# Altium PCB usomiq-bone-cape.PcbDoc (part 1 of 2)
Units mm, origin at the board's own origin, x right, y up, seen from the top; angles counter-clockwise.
Board outline 86.36 x 54.61 mm, 2 copper layers (Top Layer, Bottom Layer); 72 components, 131 nets, 473 pads, 192 vias.
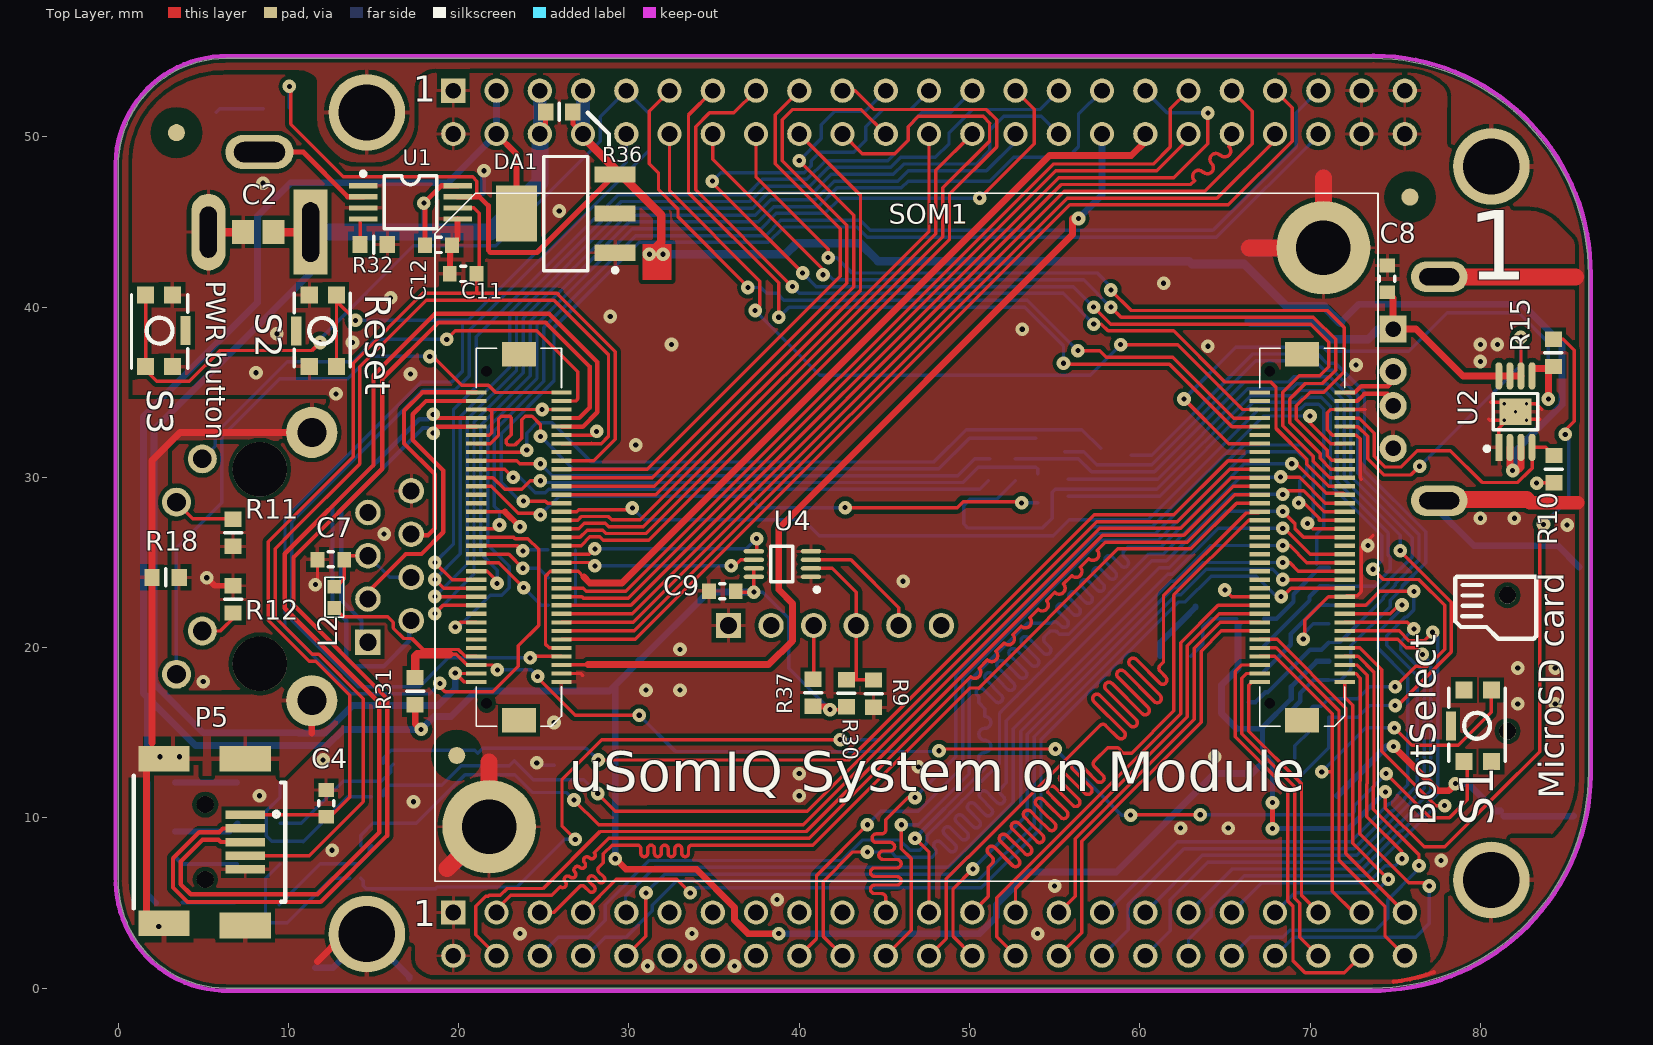
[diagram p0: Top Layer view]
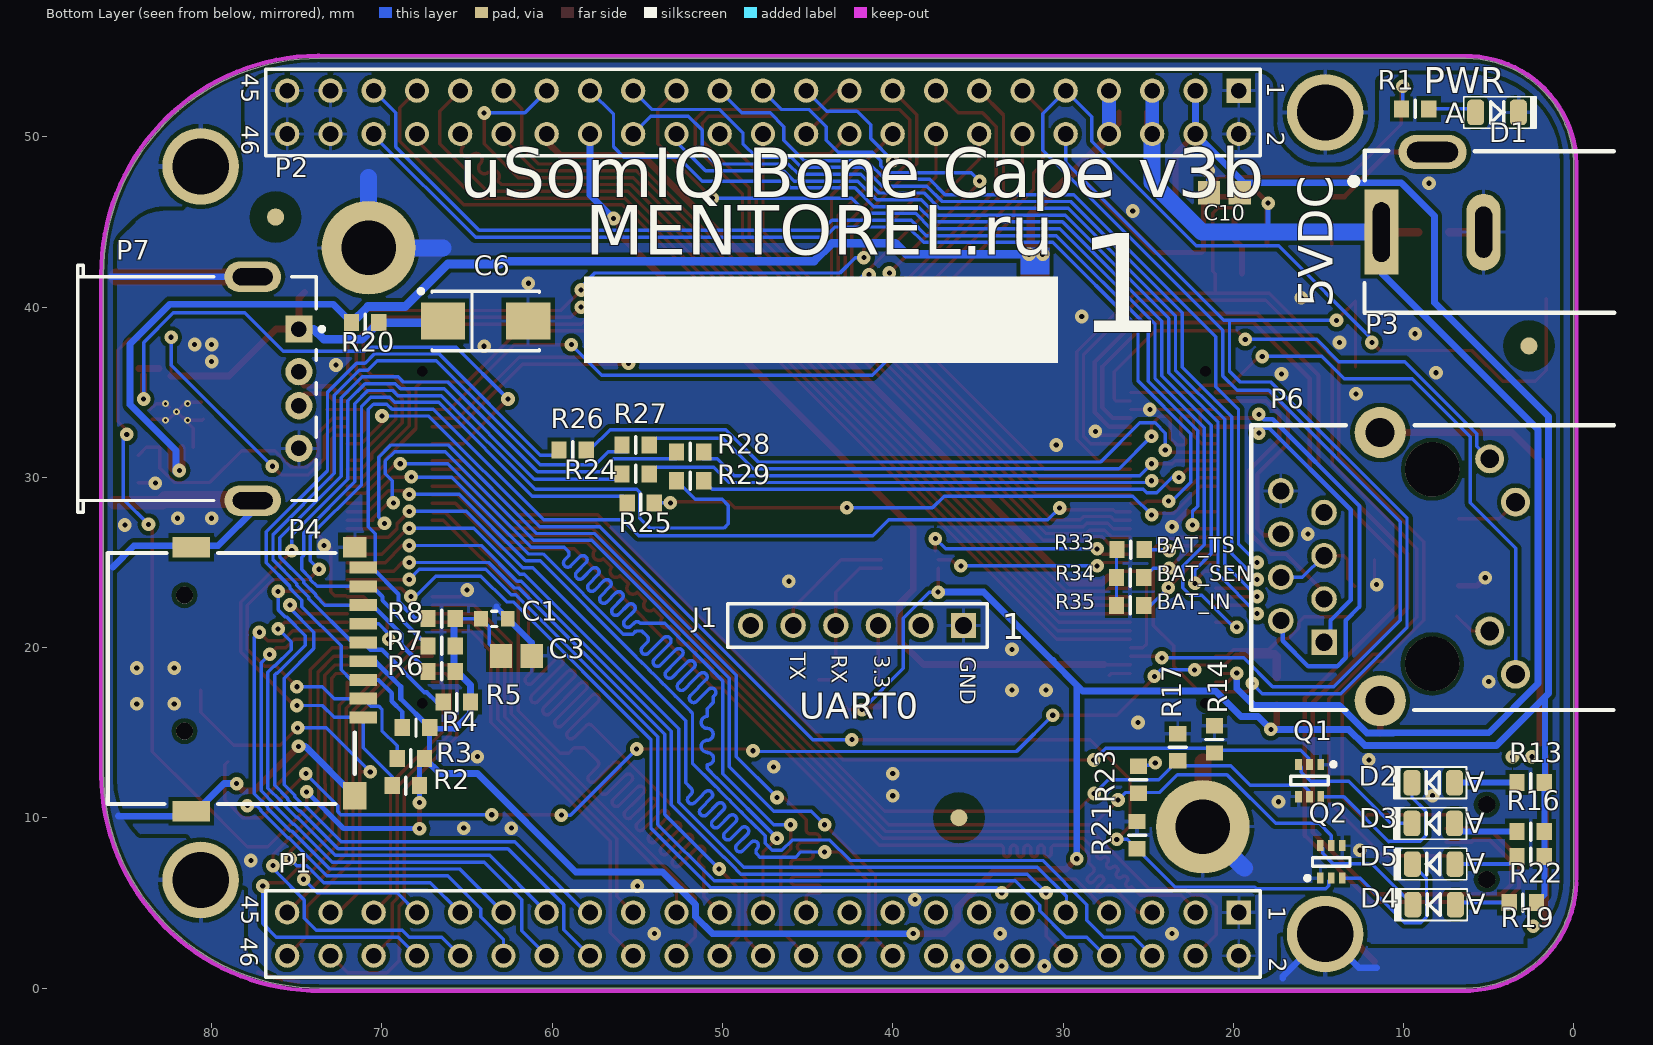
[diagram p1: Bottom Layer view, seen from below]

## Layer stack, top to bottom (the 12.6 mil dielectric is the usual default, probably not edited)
Top Solder: solder mask 0.0102, Solder Resist, Dk 3.5
Top Layer: signal copper 0.0356
Dielectric1: dielectric 0.32, FR-4, Dk 4.8
Bottom Layer: signal copper 0.0356
Bottom Solder: solder mask 0.0102, Solder Resist, Dk 3.5

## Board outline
0,6.35 0,48.26 cw(c6.35,48.26) 6.35,54.61 73.66,54.61 cw(c73.66,41.91) 86.36,41.91 86.36,12.7 cw(c73.66,12.7) 73.66,0 6.35,0 cw(c6.35,6.35)

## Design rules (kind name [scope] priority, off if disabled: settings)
AssemblyTestPointUsage [All] p1 off:
AssemblyTestPointUsage AssemblyTestPointUsage_1 [All] p2 off:
AssemblyTestpoint [All] p1 off: testpointundercomponent=TRUE minsize=1.016 maxsize=2.54 preferedsize=1.524 minholesize=0 maxholesize=1.016 preferedholesize=0.813 testpointgrid=0.025 usegrid=TRUE gridtolerance=0 allowsidetop=TRUE allowsidebottom=TRUE
AssemblyTestpoint AssemblyTestpoint_1 [All] p2 off: testpointundercomponent=TRUE minsize=1.016 maxsize=2.54 preferedsize=1.524 minholesize=0 maxholesize=1.016 preferedholesize=0.813 testpointgrid=0.025 usegrid=TRUE gridtolerance=0 allowsidetop=TRUE allowsidebottom=TRUE
Clearance Clearance_2 [InPolygon] p1: gap=0.25
Clearance Clearance_1 [InPolygon vs OnLayer('Keep-Out Layer')] p2: gap=0.25
Clearance [All] p3: gap=0.2
ComponentClearance [All] p1 off: gap=0.254 collisioncheckmode=3 verticalgap=0.254 showdistances=FALSE
ComponentClearance ComponentClearance_1 [All] p2 off: gap=0.254 collisioncheckmode=3 verticalgap=0.254 showdistances=FALSE
DiffPairsRouting [InNetClass('DIFF')] p1: maxlimit=0.254 minlimit=0.254 mostfreqgap=0.254 toplayer_minwidth=0.381 toplayer_maxwidth=0.381 toplayer_prefwidth=0.381 bottomlayer_minwidth=0.381 bottomlayer_maxwidth=0.381 bottomlayer_prefwidth=0.381 maxuncoupledlength=12.7
FabricationTestPointUsage [All] p1 off: valid=0 allowmultiple=FALSE
FabricationTestPointUsage FabricationTestPointUsage_1 [All] p2 off: valid=0 allowmultiple=FALSE
FabricationTestpoint [All] p1 off: side=3 testpointundercomponent=TRUE minsize=1.016 maxsize=2.54 preferedsize=1.524 minholesize=0 maxholesize=1.016 preferedholesize=0.813 testpointgrid=0.025 allowsidetop=TRUE allowsidebottom=TRUE usegrid=TRUE gridtolerance=0
FabricationTestpoint FabricationTestpoint_1 [All] p2 off: side=3 testpointundercomponent=TRUE minsize=1.016 maxsize=2.54 preferedsize=1.524 minholesize=0 maxholesize=1.016 preferedholesize=0.813 testpointgrid=0.025 allowsidetop=TRUE allowsidebottom=TRUE usegrid=TRUE gridtolerance=0
FanoutControl Fanout_LCC [IsLCC] p1: bgadir=Out bgaviamode=Centered fanoutstyle=Auto fanoutdirection=Alternating viagrid=0.025 // Fanout_LCC (Default Rule)
FanoutControl Fanout_BGA [IsBGA] p2: bgadir=Out bgaviamode=Centered fanoutstyle=Auto fanoutdirection=Alternating viagrid=0.025 // Fanout_BGA (Default Rule)
FanoutControl Fanout_Default [All] p4: bgadir=Out bgaviamode=Centered fanoutstyle=Auto fanoutdirection=Alternating viagrid=0.025 // Fanout_Default (Default Rule)
FanoutControl Fanout_Small [(CompPinCount < 5)] p5: bgadir=Out bgaviamode=Centered fanoutstyle=Auto fanoutdirection=OutThenIn viagrid=0.025 // Fanout_Small (Default Rule)
FanoutControl Fanout_BGA_1 [IsBGA] p6: bgadir=Out bgaviamode=Centered fanoutstyle=Auto fanoutdirection=Alternating viagrid=0.025 // Fanout_BGA (Default Rule)
FanoutControl Fanout_LCC_1 [IsLCC] p7: bgadir=Out bgaviamode=Centered fanoutstyle=Auto fanoutdirection=Alternating viagrid=0.025 // Fanout_LCC (Default Rule)
FanoutControl Fanout_SOIC_1 [IsSOIC] p8: bgadir=Out bgaviamode=Centered fanoutstyle=Auto fanoutdirection=Alternating viagrid=0.025 // Fanout_SOIC (Default Rule)
FanoutControl Fanout_Small_1 [(CompPinCount < 5)] p9: bgadir=Out bgaviamode=Centered fanoutstyle=Auto fanoutdirection=OutThenIn viagrid=0.025 // Fanout_Small (Default Rule)
FanoutControl Fanout_Default_1 [All] p10: bgadir=Out bgaviamode=Centered fanoutstyle=Auto fanoutdirection=Alternating viagrid=0.025 // Fanout_Default (Default Rule)
Height [All] p1 off: minheight=0 maxheight=25.4 prefheight=12.7
Height Height_1 [All] p2 off: minheight=0 maxheight=25.4 prefheight=12.7
HoleSize [All] p1 off: absolutevalues=TRUE maxlimit=2.54 minlimit=0.025 maxpercent=80.000 minpercent=20.000
HoleSize HoleSize_1 [All] p2 off: absolutevalues=TRUE maxlimit=2.54 minlimit=0.025 maxpercent=80.000 minpercent=20.000
HoleToHoleClearance [All] p1 off: gap=0.254 allowstackedmicrovias=TRUE
HoleToHoleClearance HoleToHoleClearance_1 [All] p2 off: gap=0.254 allowstackedmicrovias=TRUE
LayerPairs [All] p1 off: enforce=TRUE
LayerPairs LayerPairs_1 [All] p2 off: enforce=TRUE
Length Length_MMC1 [(InNetClass('MMC1'))] p1: maxlimit=62.1 minlimit=56.1
MinimumSolderMaskSliver [All] p1 off: minsoldermaskwidth=0.254
MinimumSolderMaskSliver MinimumSolderMaskSliver_1 [All] p2 off: minsoldermaskwidth=0.254
NetAntennae [All] p1 off: netantennaetolerance=0
NetAntennae NetAntennae_1 [All] p2 off: netantennaetolerance=0
PasteMaskExpansion PasteMaskExpansion_1 [All] p2: expansion=0
PlaneConnect [All] p1: planeconnectstyle=Relief reliefexpansion=0.2 reliefentries=4 reliefconductorwidth=0.2 reliefairgap=0.2
PolygonConnect PolygonConnect_EARTH [All vs InNet(EARTH)] p1: connectstyle=Relief reliefconductorwidth=0.254 reliefentries=4 polygonreliefangle="90 Angle" airgapwidth=0.254
PolygonConnect PolygonConnect_Via [IsVia] p2: connectstyle=Direct reliefconductorwidth=0.254 reliefentries=4 polygonreliefangle="90 Angle" airgapwidth=0.254
PolygonConnect [All] p3: connectstyle=Relief reliefconductorwidth=0.2 reliefentries=4 polygonreliefangle="90 Angle" airgapwidth=0.254
RoutingPriority RoutingPriority_1 [All] p2: routingpriority=0
RoutingTopology RoutingTopology_1 [All] p2: topology=Shortest
RoutingVias [All] p1: holewidth=0.4 width=0.8 viastyle="Through Hole" minholewidth=0.4 minwidth=0.8 maxholewidth=0.4 maxwidth=0.8
SilkToSilkClearance [All] p1 off: silktosilkclearance=0.254
SilkToSilkClearance SilkToSilkClearance_1 [All] p2 off: silktosilkclearance=0.254
SilkToSolderMaskClearance SilkscreenOverComponentPads [IsPad] p1 off: minsilkscreentomaskgap=0.1 clearancetoexposedcopper=TRUE
SilkToSolderMaskClearance SilkscreenOverComponentPads_1 [IsPad] p2 off: minsilkscreentomaskgap=0.1 clearancetoexposedcopper=TRUE
SolderMaskExpansion [All] p1: expansion=0.102
SolderMaskExpansion SolderMaskExpansion_1 [All] p2: expansion=0.102
UnRoutedNet UnRoutedNet_1 [All] p2:
Width Width_diff [InNetClass('DIFF')] p1: maxlimit=0.254 minlimit=0.254 preferedwidth=0.254
Width [All] p2: maxlimit=1 minlimit=0.2 preferedwidth=0.2
10 further rules are at their usual default settings.

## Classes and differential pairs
component class bone_capes: P1 P2
component class usomiq: SOM1
differential pair ETH_RX: +ETH_RX_P -ETH_RX_N
differential pair ETH_TX: +ETH_TX_P -ETH_TX_N
differential pair USB0_D: +USB0_D_P -USB0_D_N
differential pair USB1: +USB1_P -USB1_N

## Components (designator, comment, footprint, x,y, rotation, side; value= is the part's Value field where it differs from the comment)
C1 "C0603" CC1608-0603 63.4,21.7 r180 bottom
C2 "C0805" CC2012-0805 8.23,44.399 r0 top
C3 "C0805" CC2012-0805 62.1,19.5 r0 bottom
C4 "C0603" CC1608-0603 12.219,10.855 r90 top locked
C6 "Cap_C" Cap_C 63.914,39.182 r180 bottom locked
C7 "C0603" CC1608-0603 12.497,25.171 r180 top
C8 "C0603" CC1608-0603 74.539,41.657 r270 top locked
C9 "C0603" CC1608-0603 35.484,23.317 r0 top
C10 "C0805" CC2012-0805 20.523,46.711 r180 bottom
C11 "C0603" CC1608-0603 20.269,41.961 r0 top
C12 "C0603" CC1608-0603 18.821,43.637 r180 top
D1 "LED0805" LED0805 5.766,51.435 r180 bottom
D2 "LED0805" LED0805 7.01,12.065 r0 bottom
D3 "LED0805" LED0805 7.01,9.677 r0 bottom
D4 "LED0805" LED0805 6.96,4.902 r0 bottom
D5 "LED0805" LED0805 6.985,7.29 r0 bottom
DA1 "LM1117" SOT230P700X160-4N 26.289,45.491 r180 top
J1 "HEADER 6" DIP6 35.85,21.3 r270 bottom locked
L2 "BLM18A-FB" CHIP0603 12.7,22.327 r90 top
P1 "HDR_46_F_2_0.1_0.1" DIP46 19.685,4.445 r270 bottom locked
P2 "HDR_46_F_2_0.1_0.1" DIP46 19.685,52.705 r270 bottom locked
P3 "PJ-002A" PJ-002A 11.303,44.399 r90 bottom
P4 "" TFC08WP01F-A-R1K-H 71.1,15.9 r270 bottom locked
P5 "MiniUSB-B" "MINI-USB-B5 SMT" 1.219,13.081 r0 top
P6 "CONN_RJ45_MAG_WE_0" TRJ0011ABNL 14.675,20.315 r90 bottom locked
P7 "CONN_54819-0578_2" USB2.5-2H4C 87.869,35.205 r0 bottom locked
Q1 "RN1907" SOT363-6L 15.519,12.192 r270 bottom
Q2 "RN1907" SOT363-6L 14.249,7.417 r90 bottom
R1 "R0603" RESC1608X55N 9.322,51.638 r0 bottom
R2 "R0603" RESC1608X55N 68.6,11.9 r180 bottom
R3 "R0603" RESC1608X55N 68.3,13.5 r180 bottom
R4 "R0603" RESC1608X55N 68,15.3 r180 bottom
R5 "R0603" RESC1608X55N 65.6,16.8 r180 bottom
R6 "R0603" RESC1608X55N 66.5,18.6 r180 bottom
R7 "R0603" RESC1608X55N 66.5,20.1 r180 bottom
R8 "R0603" RESC1608X55N 66.5,21.7 r180 bottom
R9 "R0603" RESC1608X55N 44.374,17.297 r90 top
R10 "R0603" RESC1608X55N 84.314,30.482 r90 top locked
R11 "R0603" RESC1608X55N 6.756,26.746 r90 top
R12 "R0603" RESC1608X55N 6.756,22.835 r270 top
R13 "R0603" RESC1608X55N 2.54,12.09 r180 bottom
R14 "R0603" RESC1608X55N 21.114,14.607 r270 bottom
R15 "R0603" RESC1608X55N 84.289,37.307 r90 top
R16 "R0603" RESC1608X55N 2.54,9.195 r180 bottom
R17 "R0603" RESC1608X55N 23.266,14.148 r270 bottom
R18 "R0603" RESC1608X55N 2.794,24.13 r180 top locked
R19 "R0603" RESC1608X55N 2.997,5.029 r180 bottom
R20 "R0603" RESC1608X55N 70.989,39.082 r0 bottom
R21 "R0603" RESC1608X55N 25.654,8.992 r270 bottom
R22 "R0603" RESC1608X55N 2.54,7.722 r180 bottom
R23 "R0603" RESC1608X55N 25.578,12.243 r270 bottom
R24 "R0603" RESC1608X55N 55.1,30.2 r180 bottom
R25 "R0603" RESC1608X55N 54.8,28.5 r180 bottom
R26 "R0603" RESC1608X55N 58.8,31.6 r180 bottom
R27 "R0603" RESC1608X55N 55.1,31.9 r180 bottom
R28 "R0603" RESC1608X55N 51.9,31.5 r180 bottom
R29 "R0603" RESC1608X55N 51.9,29.8 r180 bottom
R30 "R0603" RESC1608X55N 42.774,17.323 r270 top
R31 "R0603" RESC1608X55N 17.45,17.45 r90 top
R32 "R0603" RESC1608X55N 15.011,43.663 r0 top
R33 "R0603" RESC1608X55N 26.035,25.756 r0 bottom
R34 "R0603" RESC1608X55N 26.06,24.105 r0 bottom
R35 "R0603" RESC1608X55N 26.06,22.479 r0 bottom
R36 "R0603" RESC1608X55N 25.908,51.46 r0 top
R37 "R0603" RESC1608X55N 40.818,17.348 r270 top
S1 "SW_KT11P2JM_2" KMR231GLFS 79.045,13.31 r90 top
S2 "SW_KT11P2JM_2" KMR231GLFS 11.227,36.5 r90 top
S3 "SW_KT11P2JM_2" KMR231GLFS 3.2,40.716 r270 top
SOM1 "som-am335x" am3359_module-sockets 21.789,9.482 r0 top locked
U1 "TPS211xA" TSSOP-8 17.17,46.152 r270 top
U2 "TPS2051B" R-PDSO-G8 81.089,31.757 r90 top
U4 "IC_SN74LVC2G241_1" SOP127P600-8N 39.014,24.907 r180 top locked

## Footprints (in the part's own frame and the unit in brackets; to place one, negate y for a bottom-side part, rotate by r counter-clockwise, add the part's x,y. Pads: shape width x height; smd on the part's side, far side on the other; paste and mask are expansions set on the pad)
am3359_module-sockets [mm]
  rect 1.2x0.25 smd paste+0 mask+0.02: A1(4.25,8.5) A2(-0.75,8.5) A3(4.25,9) A4(-0.75,9) A5(4.25,9.5) A6(-0.75,9.5) A7(4.25,10) A8(-0.75,10) A9(4.25,10.5) A10(-0.75,10.5) A11(4.25,11) A12(-0.75,11) A13(4.25,11.5) A14(-0.75,11.5) A15(4.25,12) A16(-0.75,12) A17(4.25,12.5) A18(-0.75,12.5) A19(4.25,13) A20(-0.75,13) A21(4.25,13.5) A22(-0.75,13.5) A23(4.25,14) A24(-0.75,14) A25(4.25,14.5) A26(-0.75,14.5) A27(4.25,15) A28(-0.75,15) A29(4.25,15.5) A30(-0.75,15.5) A31(4.25,16) A32(-0.75,16) A33(4.25,16.5) A34(-0.75,16.5) A35(4.25,17) A36(-0.75,17) A37(4.25,17.5) A38(-0.75,17.5) A39(4.25,18) A40(-0.75,18) A41(4.25,18.5) A42(-0.75,18.5) A43(4.25,19) A44(-0.75,19) A45(4.25,19.5) A46(-0.75,19.5) A47(4.25,20) A48(-0.75,20) A49(4.25,20.5) A50(-0.75,20.5) A51(4.25,21) A52(-0.75,21) A53(4.25,21.5) A54(-0.75,21.5) A55(4.25,22) A56(-0.75,22) A57(4.25,22.5) A58(-0.75,22.5) A59(4.25,23) A60(-0.75,23) A61(4.25,23.5) A62(-0.75,23.5) A63(4.25,24) A64(-0.75,24) A65(4.25,24.5) A66(-0.75,24.5) A67(4.25,25) A68(-0.75,25) A69(4.25,25.5) A70(-0.75,25.5) B1(50.25,8.5) B2(45.25,8.5) B3(50.25,9) B4(45.25,9) B5(50.25,9.5) B6(45.25,9.5) B7(50.25,10) B8(45.25,10) B9(50.25,10.5) B10(45.25,10.5) B11(50.25,11) B12(45.25,11) B13(50.25,11.5) B14(45.25,11.5) B15(50.25,12) B16(45.25,12) B17(50.25,12.5) B18(45.25,12.5) B19(50.25,13) B20(45.25,13) B21(50.25,13.5) B22(45.25,13.5) B23(50.25,14) B24(45.25,14) B25(50.25,14.5) B26(45.25,14.5) B27(50.25,15) B28(45.25,15) B29(50.25,15.5) B30(45.25,15.5) B31(50.25,16) B32(45.25,16) B33(50.25,16.5) B34(45.25,16.5) B35(50.25,17) B36(45.25,17) B37(50.25,17.5) B38(45.25,17.5) B39(50.25,18) B40(45.25,18) B41(50.25,18.5) B42(45.25,18.5) B43(50.25,19) B44(45.25,19) B45(50.25,19.5) B46(45.25,19.5) B47(50.25,20) B48(45.25,20) B49(50.25,20.5) B50(45.25,20.5) B51(50.25,21) B52(45.25,21) B53(50.25,21.5) B54(45.25,21.5) B55(50.25,22) B56(45.25,22) B57(50.25,22.5) B58(45.25,22.5) B59(50.25,23) B60(45.25,23) B61(50.25,23.5) B62(45.25,23.5) B63(50.25,24) B64(45.25,24) B65(50.25,24.5) B66(45.25,24.5) B67(50.25,25) B68(45.25,25) B69(50.25,25.5) B70(45.25,25.5)
  round 5.5 hole 3.2 mask+0.05: DGND(0,0) DGND(49,34)
  rect 2x1.45 smd mask+0.02: DGND(1.75,6.25) DGND(1.75,27.75) DGND(47.75,6.25) DGND(47.75,27.75)
  rect 0x0.25 hole 0.625 mask+0.02: NC(-0.15,7.25) NC(-0.15,26.75) NC(45.85,7.25) NC(45.85,26.75)
  silkscreen extent -3.17,-3.2 52.2,37.2, body extent -1.12,5.89 50.58,28.13, height 3.5
Cap_C [mm] "Capacitor, SM Tantalum; Body 6.0 x 3.2 mm (LxW typ)"
  rect 2.6x2.2 smd: 1(-2.5,0) 2(2.5,0)
  silkscreen extent -3.93,-1.75 3.15,1.87, body extent -3.15,-1.75 3.15,1.75, height 2.8
CC1608-0603 [mil] "Chip Capacitor, 2-Leads, Body 1,6x0,8mm, IPC Medium Density"
  rect 32x36 smd: 1(-31,0) 2(31,0)
  silkscreen extent -6,-18 6,17, body extent -31,-16 31,16, height 31
CC2012-0805 [mm] "Chip Capacitor, 2-Leads, Body 2,0x1,25mm, IPC Medium Density"
  rect 1.3x1.4 smd: 1(-0.9,0) 2(0.9,0)
  body extent -1,-0.6 1,0.6, height 1.2
CHIP0603 [mm]
  rect 0.8x0.8 smd: 1(0,0) 2(1.25,0)
  silkscreen extent -0.55,-0.55 1.8,0.55, body extent -0.53,-0.5 1.75,0.51, height 0.95
DIP6 [mm]
  rect 1.48x1.48 hole 0.98: 1(0,0)
  round 1.48 hole 0.98: 2(0,-2.5) 3(0,-5) 4(0,-7.5) 5(0,-10) 6(0,-12.5)
  silkscreen extent -1.27,-13.84 1.27,1.4, body extent -1.15,-13.72 1.12,1.28, height 8
DIP46 [mm]
  rect 1.42x1.42 hole 0.92: 1(0,0)
  round 1.42 hole 0.92: 2(2.54,0) 3(0,-2.54) 4(2.54,-2.54) 5(0,-5.08) 6(2.54,-5.08) 7(0,-7.62) 8(2.54,-7.62) 9(0,-10.16) 10(2.54,-10.16) 11(0,-12.7) 12(2.54,-12.7) 13(0,-15.24) 14(2.54,-15.24) 15(0,-17.78) 16(2.54,-17.78) 17(0,-20.32) 18(2.54,-20.32) 19(0,-22.86) 20(2.54,-22.86) 21(0,-25.4) 22(2.54,-25.4) 23(0,-27.94) 24(2.54,-27.94) 25(0,-30.48) 26(2.54,-30.48) 27(0,-33.02) 28(2.54,-33.02) 29(0,-35.56) 30(2.54,-35.56) 31(0,-38.1) 32(2.54,-38.1) 33(0,-40.64) 34(2.54,-40.64) 35(0,-43.18) 36(2.54,-43.18) 37(0,-45.72) 38(2.54,-45.72) 39(0,-48.26) 40(2.54,-48.26) 41(0,-50.8) 42(2.54,-50.8) 43(0,-53.34) 44(2.54,-53.34) 45(0,-55.88) 46(2.54,-55.88)
  silkscreen extent -1.27,-57.15 3.81,1.27, body extent -1.27,-57.15 3.81,1.27, height 8.51
KMR231GLFS [mm] "Tactile Switches"
  rect 1x1 smd: 1(0,0) 2(0,-1.6) 3(4.2,0) 4(4.2,-1.6)
  rect 1.7x0.6 smd: 5(2.1,0.762)
  silkscreen extent 0,-2.41 4.32,0.89, body extent 0.13,-2.29 4.06,0.76, height 1.5
LED0805 [mm]
  rrect50% 1x1.5 smd: 1(0,0) 2(2.5,0)
  silkscreen extent -0.7,-0.92 3.55,0.92, body extent -0.64,-0.89 3.17,0.89, height 1.1
"MINI-USB-B5 SMT" [mm]
  rect 2.3x0.5 smd: 1(6.25,-2.9) 2(6.25,-3.7) 3(6.25,-4.5) 4(6.25,-5.3) 5(6.25,-6.1)
  rect 3x1.5 smd: 6(1.475,-9.275) 7(6.25,-9.4) 8(6.25,0.4) 9(1.475,0.4)
  round 1 hole 1 unplated: SYSPAD10(3.9,-6.7) SYSPAD11(3.9,-2.3)
  silkscreen extent -0.3,-8.4 8.6,-0.6, body extent -1.84,-9.79 7.36,0.91, height 3.95
PJ-002A [mm] "DC POWER JACK"
  rect 5x2 hole 1 slot 3.5 at 0 deg: 1(0,0)
  oval 4.5x2 hole 1 slot 3 at 0 deg: 2(0,-6)
  oval 2x4 hole 1.2 slot 3 at 90 deg: 3(4.7,-3)
  silkscreen extent -4.72,-13.67 4.77,1.81, body extent -4.37,-13.59 4.93,0.41, height 11
R-PDSO-G8 [mm]
  rect 1.6x0.4 smd: 1(0,0)
  oval 1.6x0.4 smd: 2(0,-0.65) 3(0,-1.3) 4(0,-1.95) 5(4.2,-1.95) 6(4.2,-1.3) 7(4.2,-0.65) 8(4.2,0)
  rect 1.57x1.89 smd: 9(2.1,-0.975)
  silkscreen extent -0.2,-2.28 3.17,0.82, body extent 0.45,-2.75 3.73,0.8, height 1.1
RESC1608X55N [mm] "Chip Resistor, EIA 0603, Metric 1608, Body 1.6x0.8mm, IPC Medium Density"
  rect 0.9x1 smd: 1(-0.8,0) 2(0.8,0)
  silkscreen extent 0,-0.5 0,0.5, body extent -0.87,-0.47 0.88,0.48, height 0.55
SOP127P600-8N [mm]
  oval 1.2x0.25 smd mask+0.05: 1(-1.675,0.75) 2(-1.675,0.25) 3(-1.675,-0.25) 4(-1.675,-0.75) 5(1.675,-0.75) 6(1.675,-0.25) 7(1.675,0.25) 8(1.675,0.75)
  silkscreen extent -2.15,-1.05 0.67,1.62, body extent -1.55,-1.05 1.55,1.05, height 0.9
SOT230P700X160-4N [mm] "SOT223, 4-Leads, Body 6,7x7,3mm (max), Pitch 2,30mm, IPC Medium Density"
  rect 2.4x0.95 smd: 1(-2.9,2.3) 2(-2.9,0) 3(-2.9,-2.3)
  rect 2.4x3.3 smd: 4(2.9,0)
  silkscreen extent -3.03,-3.35 1.3,3.45, body extent -3.48,-3.35 3.48,3.35, height 1.7
SOT363-6L [mm] "SOT363, 6-Leads, Body 2x1.3mm, Pitch 0.65mm, Lead Span 2.1mm, IPC High Density"
  rect 0.65x0.4 smd: 1(-0.95,0.65) 2(-0.95,0) 3(-0.95,-0.65) 4(0.95,-0.65) 5(0.95,0) 6(0.95,0.65)
  silkscreen extent -1.07,-1.1 0.25,1.52, body extent -1.15,-1.1 1.15,1.1, height 1
TFC08WP01F-A-R1K-H [mm]
  rect 0.7x1.6 smd paste+0 mask+0.064: 1(0,0) 2(-1.1,0) 3(-2.2,0) 4(-3.3,0) 5(-4.4,0) 6(-5.5,0) 7(-6.6,0) 8(-7.7,0) 9(-8.8,0)
  rect 1.2x1.4 smd paste+0 mask+0.064: 10(-10,-0.5)
  rect 1.2x2.2 smd paste+0 mask+0.064: 11(-10,-10.1) 12(5.5,-10.1)
  rect 1.6x1.4 smd paste+0 mask+0.064: 13(4.6,-0.5)
  round 1 hole 1 unplated: free(-7.18,-10.5) free(0.8,-10.5)
  silkscreen extent -9.65,-15 5.08,-0.51, body extent -9.65,-14.99 5.08,-0.51, height 1.8
TRJ0011ABNL [mm] "TRJ0011ABNL RJ-45 magnet"
  round 3.2 hole 3.2 unplated: 0(-1.27,-6.35) 0(10.16,-6.35)
  rect 1.5x1.5 hole 1: 1(0,0)
  round 1.5 hole 1: 2(1.27,2.54) 3(2.54,0) 4(3.81,2.54) 5(5.08,0) 6(6.35,2.54) 7(7.62,0) 8(8.89,2.54)
  round 1.7 hole 1.1: 9(-1.88,-11.25) 10(0.66,-9.73) 11(8.23,-11.25) 12(10.77,-9.73)
  round 3 hole 1.7: 13(-3.43,-3.3) 14(12.32,-3.3)
  silkscreen extent -3.98,-17.02 12.75,4.28, body extent -3.7,-17.1 12.5,4.06, height 13.4
TSSOP-8 [mm] "Shrink Small Outline; 8 Leads; Body Width 4.4 mm; Pitch 0.65 mm"
  rect 0.3x1.65 smd: 1(-0.975,-2.775) 2(-0.325,-2.775) 3(0.325,-2.775) 4(0.975,-2.775) 5(0.975,2.775) 6(0.325,2.775) 7(-0.325,2.775) 8(-0.975,2.775)
  silkscreen extent -1.8,-2.9 1.55,1.55, body extent -1.55,-3.22 1.55,3.28, height 1.2
USB2.5-2H4C [mm] "Connector; USB1.1, Type A, Thru-Hole; 4 Position; Right Angle"
  rect 1.6x1.6 hole 0.92: 1(-12.99,-3.5)
  round 1.6 hole 0.92: 2(-12.99,-1) 3(-12.99,1) 4(-12.99,3.5)
  oval 3.34x1.8 hole 1 slot 2.34 at 0 deg: 5(-10.28,6.57) 6(-10.28,-6.57)
  silkscreen extent -14.46,-7.25 0,7.25, body extent -14,-7.9 0.13,7.9, height 7.55

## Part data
C6: "Tantalum Capacitor Case C"
D1 D2 D3 D4 D5: "LED 0805"
DA1: "800mA Low-Dropout Linear Regulator"
J1: "CONN HEADER 6POS, VERTICAL,  .100 STR TIN"
L2: "Chip EMIFILr Inductor Type"
P1 P2: "NN HEADER FMAL 46PS.1\" DL GOLD"
P3: "DC POWER JACK"
P4: library part TFC08WP01F-R1K-H-CN, "Connector for microSD™ Card (Push-push Type)"
P5: "Mini USB Type B CONNECTOR"
P6: "RJ-45 10/100 W/Magnetics"
P7: "USB Type A Connectors"
Q1 Q2: "Transistor Silicon NPN"
S1 S2 S3: "SMD button"
U1: "Single Channel, Current-Limited USB Power Distribution Switch"
U2: "CURRENT-LIMITED, POWER-DISTRIBUTION SWITCHES"
U4: "Dual Buffer/Driver With 3-State Outputs"

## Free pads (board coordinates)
  round 1 smd far side mask+1: 0(2.642,37.719) 0(36.119,10.008) 0(76.251,45.288)
  round 1 smd mask+1: 0(3.429,50.241) 0(19.888,13.665) 0(75.87,46.457)
  round 4.5 hole 3.3: free(14.605,3.175) free(14.605,51.435) free(80.645,6.35) free(80.645,48.26)

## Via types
v1: diameter 0.8, hole 0.3, Top Layer to Bottom Layer, tented both sides, 187 vias
v2: diameter 0.4, hole 0.2, Top Layer to Bottom Layer, 5 vias

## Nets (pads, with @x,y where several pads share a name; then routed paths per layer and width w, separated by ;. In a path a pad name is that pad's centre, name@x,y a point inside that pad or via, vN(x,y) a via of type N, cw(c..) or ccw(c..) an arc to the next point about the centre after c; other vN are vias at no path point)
1V8_OUT: P2.32 SOM1.A5 | length 52.3
  Top Layer w0.2: SOM1.A5@26.039,18.982 26.057,19 27.6,19
  Top Layer w0.4: 27.6,19 38.2,19 39.6,20.4 39.6,22.6 38.8,23.4 38.8,27 56.059,44.259 56.059,45.2 v1(56.4,45.2)
  Bottom Layer w0.4: v1(56.4,45.2) 57.785,46.585 P2.32@57.785,50.165
3V3_OUT: L2.1 R31.2 S1.1 SOM1.A6 SOM1.A8 | length 81.8
  Top Layer w0.2: L2.1@12.763,22.263 13.222,21.805 15.838,21.805 16.165,21.478 16.165,21.15 16.78,20.535 17.26,20.535 17.907,19.888 19.984,19.888 20.39,19.482 SOM1.A8@21.039,19.482 ; 19.45,19.609 19.863,19.609 20.49,18.982 SOM1.A6@21.039,18.982 21.988,18.982 v1(22.276,18.694) ; v1(24.638,18.313) 24.638,18.234 26.844,16.027 v1(30.607,16.027) ; v1@47.955,13.995 48.006,14.046 v1(55.042,14.046) ; v1(59.461,10.16) 59.487,10.185 v1(63.551,10.185) ; v1(74.473,12.598) 77.052,10.019 78.192,10.019 79.237,11.064 79.237,13.118 S1.1@79.045,13.31
  Top Layer w0.5: R31.2@17.45,18.25 17.45,19.482 17.568,19.6 19.441,19.6
  Bottom Layer w0.2: v1(22.276,18.694) 24.257,18.694 v1(24.638,18.313) ; v1(30.607,16.027) 32.734,13.9 47.86,13.9 v1@47.955,13.995 ; v1(55.042,14.046) 58.928,10.16 v1(59.461,10.16) ; v1(63.551,10.185) 72.41,10.185 72.6,10.376 72.6,10.726 v1(74.473,12.598)
  other v1: 48.209,13.945
3V3_SYS: C1.1 C3.2 C9.2 C10.2 DA1.4 P2.3 P2.4 P4.4 R2.2 R3.2 R4.2 R5.2 R6.2 R7.2 R8.2 R13.2 R15.2 R16.2 R19.2 R22.2 R30.2 R31.1 R37.2 U4.7 U4.8 | length 249.5
  Top Layer w0.2: C9.2@36.271,23.317 36.327,23.261 v1(37.339,23.261) U4.8@37.339,24.157 U4.7@37.339,24.657 ; v1(41.808,16.358) 42.608,16.358 R30.2@42.774,16.523 ; v1(74.422,11.532) 74.422,10.578 76.7,8.3 77.9,8.3 80.975,11.375 ; 80.975,11.379 80.975,11.375 ; v1@83.7,27.349 83.49,27.139 83.49,13.89 80.975,11.375 ; R15.2@84.289,38.107 84.872,38.107 85.514,37.465 85.514,33.294 v1@84.95,32.73
  Top Layer w0.305: v1(67.793,9.373) v1(67.793,10.897)
  Top Layer w0.35: P2.4@22.225,50.165 23.389,49.001 DA1.4@23.389,45.491 ; R37.2@40.818,16.548 v1@41.618,16.548
  Top Layer w0.4: R31.1@17.45,16.65 17.45,15.55 v1(17.8,15.2) ; v1(29.2,7.6) 29.815,6.985 33.96,6.985 36.2,4.745 36.2,4 37,3.2 v1(38.8,3.2)
  Bottom Layer w0.2: v1(37.339,23.261) 37.86,23.261 39.39,21.731 39.39,18.776 v1(41.808,16.358) ; C3.2@63,19.5 63.7,20.2 63.7,21.213 C1.1@64.187,21.7 R8.2@65.7,21.7 ; R4.2@67.133,15.233 R4.2@67.2,15.3 ; v1(83.71,27.24) 85.19,28.72 v1@85.19,32.52
  Bottom Layer w0.305: 65.7,15.233 R4.2@67.133,15.233 ; v1(67.793,9.373) 72.263,9.373 v1(74.422,11.532) ; v1(67.793,10.897) 67.8,10.904 R2.2@67.8,11.9 67.8,13.2 R3.2@67.5,13.5 67.2,13.8 R4.2@67.2,15.3 68.9,17 68.9,17.7 70.4,19.2 P4.4@71.1,19.2
  Bottom Layer w0.35: 1.689,17.111 1.689,12.142 R13.2@1.74,12.09 R16.2@1.74,9.195 1.74,5.486 R19.2@2.223,5.004
  Bottom Layer w0.4: v1@17.6,15.2 13.226,15.2 12.282,14.256 4.544,14.256 1.689,17.111 1.5,17.3 1.5,33.58 8.179,40.259 8.179,45.341 10.137,47.299 19.359,47.299 P2.4@22.225,50.165 P2.3@22.225,52.705 ; v1(17.8,15.2) 18.55,15.95 19.55,15.95 21.05,17.45 28.85,17.45 29.2,17.8 ; v1(29.2,7.6) 29.2,17.8 ; 30.577,19.245 30.577,19.177 ; v1(37.339,23.261) 34.661,23.261 30.577,19.177 ; v1(38.8,3.2) 50.6,3.2 51.595,4.195 51.595,4.905 53.519,6.829 58.619,6.829 64.391,12.6 66.6,12.6 R3.2@67.5,13.5 ; 65.7,15.233 64.8,16.133 R5.2@64.8,16.8 64.8,17.8 65.769,18.769 65.769,21.33 R8.2@65.844,21.405 ; 29.2,17.8 30.577,19.177
  other v1: 84.99,32.52
5VDC: C2.2 C12.2 P2.5 P2.6 P3.1 R36.1 SOM1.A2 SOM1.A4 U1.8 | length 84
  Top Layer w0.2: v1(19.8,18.5) v1@19.818,18.482 ; SOM1.A2@21.039,17.982 20.318,17.982 v1@19.818,18.482 ; SOM1.A4@21.039,18.482 v1@19.818,18.482
  Top Layer w0.3: v1(17.958,46.101) 18.984,47.127 U1.8@19.945,47.127 ; C12.2@18.034,43.637 v1@18.034,46.025 ; P2.6@24.765,50.165 25.108,50.508 R36.1@25.108,51.46
  Top Layer w0.5: C2.2@9.13,44.399 P3.1@11.303,44.399
  Bottom Layer w0.3: 17.958,44.425 v1(17.958,46.101)
  Bottom Layer w0.4: P3.1@11.303,44.399 11.269,44.365 11.269,41.978 2.1,32.809 2.1,17.9 5,15 10.573,15 10.588,14.985 12.162,14.985 13.777,16.6 18.8,16.6 19.8,17.6 v1(19.8,18.5)
  Bottom Layer w0.8: P2.6@24.765,50.165 P2.5@24.765,52.705
  Bottom Layer w1: P3.1@11.303,44.399 21.844,44.399 24.765,47.32 P2.6@24.765,50.165
AIN0: P2.39 SOM1.A11 | length 58.4
  Top Layer w0.2: SOM1.A11@26.039,20.482 30.383,20.482 55.901,46 65.208,46 68.955,49.747 68.955,51.695 P2.39@67.945,52.705
AIN1: P2.40 SOM1.A13 | length 54.2
  Top Layer w0.2: SOM1.A13@26.039,20.982 30.318,20.982 55.736,46.4 64.536,46.4 67.945,49.809 P2.40@67.945,50.165
AIN2: P2.37 SOM1.A15 | length 55.8
  Top Layer w0.2: SOM1.A15@26.039,21.482 30.252,21.482 55.57,46.8 63.805,46.8 66.6,49.595 66.6,51.51 P2.37@65.405,52.705
AIN3: P2.38 SOM1.A17 | length 52.9
  Top Layer w0.2: SOM1.A17@26.039,21.982 30.186,21.982 55.404,47.2 62.999,47.2 63.22,47.421 ; 63.207,47.434 cw(c63.455,47.681) 63.702,47.929 ; 63.728,47.929 ccw(c63.976,48.177) 64.223,48.424 cw(c64.471,48.672) 64.718,48.919 ; 64.746,48.921 ccw(c64.993,49.169) 65.241,49.416 ; 65.228,49.429 65.405,49.606 P2.38@65.405,50.165
AIN4: P2.33 SOM1.A19 | length 55.2
  Top Layer w0.2: SOM1.A19@26.039,22.482 30.12,22.482 55.238,47.6 62,47.6 64,49.6 v1(64,51.4)
  Bottom Layer w0.2: P2.33@60.31,52.69 61.6,51.4 v1(64,51.4)
AIN5: P2.36 SOM1.A21 | length 47.9
  Top Layer w0.2: SOM1.A21@26.039,22.982 27.245,22.982 27.327,22.9 29.973,22.9 55.073,48 61,48 P2.36@62.8,49.8
AIN6: P2.35 SOM1.A23 | length 51.8
  Top Layer w0.2: SOM1.A23@26.039,23.482 27.311,23.482 27.493,23.3 29.807,23.3 54.907,48.4 59.2,48.4 ; 60.6,48.4 59.2,48.4 ; P2.35@62.865,52.705 61.8,51.64 61.8,49.4 60.8,48.4 59.2,48.4
B_UART0_RX: J1.4 R9.2 R30.1 U4.2 | length 9.9
  Top Layer w0.2: U4.2@40.689,24.657 41.943,24.657 43.35,23.25 J1.4@43.35,21.3 43.358,21.292 43.358,18.123 ; R30.1@42.774,18.123 43.358,18.123 ; R9.2@44.348,18.123 43.358,18.123
B_UART0_TX: J1.5 U4.3 | length 7.4
  Top Layer w0.2: U4.3@40.689,25.157 43.043,25.157 45.85,22.35 J1.5@45.85,21.3
BAT_IN: R35.1 SOM1.A30 | length 5.3
  Top Layer w0.2: SOM1.A30@21.039,24.982 22.357,24.982 v1(23.819,23.52)
  Bottom Layer w0.2: v1(23.819,23.52) 24.86,22.479 R35.1@25.26,22.479
BAT_SENSE: R34.1 SOM1.A32 | length 4.8
  Top Layer w0.2: SOM1.A32@21.039,25.482 22.956,25.482 v1(23.774,24.663) v1@23.774,24.638
  Bottom Layer w0.2: v1(23.774,24.663) 24.702,24.663 R34.1@25.26,24.105
BAT_TS: R33.1 SOM1.A34 | length 4.4
  Top Layer w0.2: SOM1.A34@21.039,25.982 23.472,25.982 v1(23.774,25.679) v1@23.825,25.73
  Bottom Layer w0.2: v1(23.774,25.679) 23.851,25.756 R33.1@25.235,25.756
CLKOUT2: P2.41 SOM1.A38 | length 67.3
  Top Layer w0.2: SOM1.A38@21.039,26.982 22.082,26.982 22.35,27.25 v1@22.4,27.3
  Bottom Layer w0.2: v1(22.4,27.2) 22.4,28 22.1,28.3 22.1,32.738 25,35.638 25,38.8 30.4,44.2 38.027,44.2 38.927,45.1 43.573,45.1 44.173,44.5 64.3,44.5 69.2,49.4 69.2,51.42 P2.41@70.485,52.705
DGND: C1.2 C2.1 C3.1 C4.2 C6.2 C7.2 C8.1 C9.1 C10.1 C11.1 C12.1 D1.2 DA1.1 J1.1 P1.1 P1.2 P2.1 P2.2 P2.43 P2.44 P2.45 P2.46 P3.2 P4.6 P4.10 P5.5 P6.8 P7.4 Q1.1 Q1.4 Q2.1 Q2.4 R9.1 R10.1 R11.1 R12.1 R14.1 R17.1 R18.1 R21.1 R23.1 R32.2 S2.1 S2.3 S3.1 S3.3 SOM1.A1 SOM1.A3 SOM1.A42 SOM1.A59 SOM1.A60 SOM1.A65 SOM1.A66 SOM1.B21 SOM1.B22 SOM1.B59 SOM1.B65 SOM1.DGND@21.789,9.482 SOM1.DGND@70.789,43.482 U1.1 U1.3 U1.5 U2.1 U2.9 U4.1 U4.4 | length 86.5
  Top Layer w0.2: v1(11.582,23.698) 11.709,23.825 C7.2@11.709,25.171 ; SOM1.A42@21.039,27.982 22.718,27.982 ; SOM1.A60@21.039,32.482 21.8,32.482 21.939,32.621 21.939,33.843 21.8,33.982 ; SOM1.A66@21.039,33.982 21.8,33.982 ; SOM1.A3@26.039,18.482 27.162,18.482 27.28,18.364 ; SOM1.A59@26.039,32.482 27.882,32.482 v1(28.1,32.7) ; SOM1.A65@26.039,33.982 v1(24.9,33.982) 21.8,33.982 ; v1@65,23.4 v1(65,23.382) 65.4,22.982 SOM1.B22@67.039,22.982 ; v1(69.6,20.5) 69.7,20.6 69.7,21.6 71.082,22.982 SOM1.B21@72.039,22.982 72.114,23.057 72.763,23.057 73,23.294 73,25.9 73.7,26.6 ; 73,29.9 72.939,29.961 72.939,32.261 72.718,32.482 SOM1.B59@72.039,32.482 71.318,32.482 71,32.8 71,33.8 71.182,33.982 SOM1.B65@72.039,33.982 73.26,33.982 ; 80.5,33.4 80.543,33.357 v2(81.414,33.357) 81.457,33.357 U2.9@81.6,33.5 ; 80.6,34.4 81.521,34.4 v2(82.064,33.857) ; U2.1@81.089,31.757 81.089,32.882 v2(82.064,33.857) ; U2.9@82.5,34.118 v2(82.714,34.332) 83.268,34.332 83.6,34 ; v1(83.31,29.66) 83.332,29.682 R10.1@84.314,29.682 ; 83.5,33.4 82.521,33.4 v2(82.064,33.857)
  Top Layer w0.35: v1(5.207,24.105) 5.677,23.635 R12.1@6.756,23.635 ; C11.1@19.482,41.961 19.482,43.51 C12.1@19.609,43.637 19.945,43.974 U1.5@19.945,45.177 ; 22.718,27.982 v1(23.6,27.1)
  Top Layer w0.5: P3.2@5.303,44.399 C2.1@7.33,44.399
  Top Layer w1: 19.329,7.022 SOM1.DGND@21.789,9.482 21.789,13.28 ; 66.444,43.482 SOM1.DGND@70.789,43.482 70.789,47.573
  Bottom Layer w0.2: v1(24.587,13.233) 24.727,13.094 R23.1@25.629,13.094 ; v1(69.6,20.5) 69.6,20.8 70.2,21.4 P4.6@71.1,21.4
  Bottom Layer w0.35: C10.1@21.423,46.711 21.423,47.941 v1(21.488,48.006) ; C3.1@61.2,19.5 61.2,20.287 C1.2@62.613,21.7 63.269,22.356 63.269,22.407
  Bottom Layer w1: 19.355,7.048 SOM1.DGND@21.789,9.482 ; 66.424,43.482 SOM1.DGND@70.789,43.482 70.789,47.599
  other v1: 31.1,1.3 33.6,1.3 36.2,1.3 23.6,3.2 33.7,3.2 54,3.2 38.7,5.2 55,6 77.7,7.5 12.573,8.103 62.4,9.4 65.2,9.4 17.348,10.947 8.306,11.303 40,11.3 40,12.6 47,13 12.04,13.411 64.4,13.6 25.6,15.6 82.2,16.7 84.4,16.7 31,17.5 33,17.5 5,18 82.2,18.8 84.4,18.8 33,19.9 46.1,23.9 73.394,26 15.621,26.67 85.1,27.2 80,27.6 82,27.6 30.4,31.9 12.8,34.9 17.17,36.068 8.103,36.144 72.7,36.6 80,36.8 64,37.7 32.5,37.8 80,37.8 81,37.8 13.767,37.922 9.322,38.43 53.1,38.7 28.905,39.446 16.002,40.538 61.4,41.4 25.908,45.644 8.509,47.269
  other v2: 82.714,33.357 81.414,34.332
EARTH: P4.11 P4.12 P4.13 P5.6 P5.7 P5.8 P5.9 P6.13 P6.14 P7.5 P7.6 pad.free R18.2 | length 107
  Top Layer w0.254: 74.905,0.381 ccw(c73.895,9.922) 77.267,0.94
  Top Layer w0.4: P5.6@1.67,3.808 P5.9@1.67,13.608 ; 1.994,14.406 R18.2@1.994,24.13 1.994,30.994 3.635,32.635 P6.14@11.375,32.635 ; 11.375,14.975 P6.13@11.375,16.885 ; 11.709,1.575 13.31,3.175 pad.free@14.605,3.175 pad.free@13.13,1.7 ; v1(74.9,14.2) 77.5,11.6 78.148,11.6 v1@78.549,12.002 ; P7.6@77.589,41.775 P7.6@77.589,42.411
  Top Layer w0.8: 82.714,28.7 82.914,28.5 85.725,28.5
  Top Layer w1: P7.5@77.589,28.635 77.654,28.7 82.714,28.7 ; P7.6@77.589,41.775 85.598,41.775
  Bottom Layer w0.4: 11.6,1.2 12.63,1.2 pad.free@14.605,3.175 17.1,0.68 17.1,0.6 ; P4.13@71.6,11.3 74.5,14.2 v1(74.9,14.2) ; P7.5@76.965,28.635 77.277,28.323 79.618,25.982 P4.11@80.464,25.982 ; P7.6@77.589,41.775 85.928,41.775 ; v1(78.537,12.014) 79.286,12.014 80.9,10.4 P4.12@81.2,10.4 ; 79.808,25.982 P4.11@80.464,25.982 ; P4.12@81.4,10.1 85.471,10.119 ; 85.804,24.742 84.564,25.982 81.2,25.982 P4.11@80.464,25.982
  other v1: 2.388,3.632 2.464,13.589 3.607,13.589
EHRPWM1A: P2.14 SOM1.B51 | length 54.2
  Top Layer w0.2: P2.14@34.925,50.165 34.925,48.675 41.4,42.2 v1(41.4,41.9) ; v1(58.3,40) 58.9,39.4 70.2,39.4 71.5,38.1 71.5,36.3 70.71,35.51 69.71,35.51 68.8,34.6 68.8,33.2 70.6,31.4 70.6,31.109 71.227,30.482 SOM1.B51@72.039,30.482
  Bottom Layer w0.2: v1(41.4,41.9) 41.4,42.2 41.55,42.05 42,41.6 56.7,41.6 v1(58.3,40)
EHRPWM1B: P2.16 SOM1.B53 | length 52
  Top Layer w0.2: P2.16@37.465,50.165 37.465,47.635 41.7,43.4 v1(41.7,42.9) ; v1(58.3,41) 59.5,39.8 71,39.8 72,38.8 72,36.2 70.8,35 70,35 69.2,34.2 69.2,33.4 71,31.6 71,31.275 71.275,31 SOM1.B53@71.8,31
  Bottom Layer w0.2: v1(41.7,42.9) 42.2,42.9 43.1,42 57.5,42 v1@58.3,41.2 ; v1@58.1,41.2 v1(58.3,41)
ETH_ALINK: P6.9 SOM1.A69 | length 37.8
  Top Layer w0.2: v1@18.4,37.2 20.183,35.417 21.753,35.417 22.188,34.982 SOM1.A69@26.039,34.982
  Bottom Layer w0.2: P6.9@3.425,18.435 3.425,25.825 6.095,28.495 6.095,32.395 9.5,35.8 13.5,35.8 14.8,37.1 v1(18.3,37.1)
ETH_RX_N: P6.2 SOM1.A64 | length 25.7
  Top Layer w0.254: v1(18.5,33.7) 18.718,33.482 SOM1.A64@21.039,33.482
  Bottom Layer w0.254: P6.2@17.1,21.3 17.1,20.4 15.6,18.9 13.9,18.9 13.4,19.4 13.4,21.6 12.592,22.408 12.592,28.31 17.69,33.408 18.208,33.408 v1(18.5,33.7) v1@18.3,33.5
ETH_RX_P: P6.1 SOM1.A62 | length 18.4
  Top Layer w0.254: v1@18.5,32.8 18.674,32.974 SOM1.A62@21.039,32.974
  Bottom Layer w0.254: P6.1@14.3,20.6 14.3,21.6 13.1,22.8 13.1,28.1 17.9,32.9 18.2,32.9 v1(18.5,32.6) v1@18.334,32.766
ETH_SPEED100: P6.12 SOM1.A67 | length 29.2
  Top Layer w0.2: v1(19.3,38.1) 19.8,38.6 24.6,38.6 27,36.2 27,34.6 26.882,34.482 SOM1.A67@26.039,34.482
  Bottom Layer w0.2: P6.12@4.945,31.085 5.695,31.835 5.695,32.561 9.934,36.8 13.8,36.8 15.1,38.1 v1(19.3,38.1)
ETH_TX_N: P6.6 SOM1.A70 | length 13.5
  Top Layer w0.254: P6.6@17.6,26.6 18.2,26.6 18.592,26.992 18.592,30.19 16.792,31.99 16.792,33.91 17.872,34.99 SOM1.A70@21.039,34.99
ETH_TX_P: P6.3 SOM1.A68 | length 17.6
  Top Layer w0.254: P6.3@14.7,23.3 16.9,25.5 17.818,25.5 19.1,26.782 19.1,30.4 17.3,32.2 17.3,33.7 18.082,34.482 SOM1.A68@21.039,34.482
GNDA_ADC: P2.34 SOM1.A9 SOM1.A27 | length 51.8
  Top Layer w0.2: SOM1.A9@26.039,19.982 25.318,19.982 25.1,20.2 25.1,24.2 25.382,24.482 SOM1.A27@26.039,24.482 27.018,24.482 27.356,24.144
  Top Layer w0.4: 27.356,24.144 27.7,23.8 29.6,23.8 54.7,48.9 59.5,48.9 60.325,49.725 P2.34@60.325,50.165
GPIO0_7: P2.42 SOM1.A43 | length 64.5
  Top Layer w0.2: v1(23.8,28.6) 25.1,28.6 25.218,28.482 SOM1.A43@26.039,28.482
  Bottom Layer w0.2: v1(23.8,28.6) 23.61,28.6 22.5,29.71 22.5,30.29 22.5,32.572 25.6,35.672 25.6,38.8 30.6,43.8 38.193,43.8 39.093,44.7 43.407,44.7 44.007,44.1 64.5,44.1 P2.42@70.5,50.1
GPIO1_16: P2.15 SOM1.B47 | length 54.6
  Top Layer w0.2: P2.15@37.465,52.705 36.16,51.4 34.732,51.4 33.915,50.583 33.915,46.885 v1(39.6,41.2) ; 57.734,39 58.134,38.6 61.984,38.6 64.984,35.6 67.7,35.6 68,35.3 68,32.869 69.8,31.069 69.8,30.778 71.096,29.482 SOM1.B47@72.039,29.482
  Bottom Layer w0.2: v1(39.6,41.2) 40,40.8 55.5,40.8 v1(57.3,39)
GPIO1_17: P2.23 SOM1.B49 | length 67.5
  Top Layer w0.2: v1(34.9,47.4) 34.9,47.3 v1(40.2,42) ; v1(57.29,40) 57.3,40 58.3,39 70.034,39 71.1,37.934 71.1,36.5 70.573,35.973 69.373,35.973 68.4,35 68.4,33.034 70.2,31.234 70.2,30.944 71.162,29.982 SOM1.B49@72.039,29.982
  Bottom Layer w0.2: v1(34.9,47.4) 35.4,47.9 40.29,47.9 40.7,48.31 40.7,48.6 41.2,49.1 43.2,49.1 43.9,49.8 43.9,50.6 44.9,51.6 46.52,51.6 P2.23@47.625,52.705 ; v1(40.2,42) 41,41.2 56.09,41.2 v1(57.29,40)
GPIO1_28: P2.12 SOM1.B66 | length 46.2
  Top Layer w0.2: P2.12@32.385,50.165 32.385,46.819 37.682,41.522 37.682,40.07 v1(37.414,39.802) ; v1(58.877,37.795) 62.223,37.795 66.036,33.982 SOM1.B66@67.039,33.982
  Bottom Layer w0.2: v1(37.414,39.802) 37.414,39.796 41.207,36.003 57.085,36.003 v1(58.877,37.795)
GPIO1_29: P1.26 SOM1.B27 | length 38.3
  Top Layer w0.2: P1.26@50.165,1.905 49.035,3.035 49.035,5.835 v1(50.2,7) ; v1(68.4,25) 68.8,25 69.318,24.482 SOM1.B27@72.039,24.482
  Bottom Layer w0.2: v1(50.2,7) 53.4,10.2 53.4,14.925 61.975,23.5 62.234,23.5 63.734,25 v1(68.4,25)
GPIO2_1: P1.18 SOM1.B39 | length 53.2
  Top Layer w0.2: P1.18@40.005,1.905 41.015,2.915 41.015,6.615 v1(44,9.6) ; v1@69.4,28.6 69.54,28.6 70.55,27.59 70.55,27.482 SOM1.B39@72.039,27.482
  Bottom Layer w0.2: v1(44,9.6) 44.8,10.4 46.99,10.4 49.594,13.004 49.594,18.206 57.688,26.3 61.075,26.3 66.275,31.5 69.262,31.5 69.8,30.962 69.8,30.21 69.4,29.81 v1@69.4,28.6
  other v1: 69.328,28.501
GPIO3_19: P2.27 SOM1.A16 | length 59.9
  Top Layer w0.2: v1(19.8,21.2) 20.082,21.482 SOM1.A16@21.039,21.482 ; v1(50.6,46.4) 53.8,49.6 53.8,51.61 P2.27@52.705,52.705
  Bottom Layer w0.2: v1(19.8,21.2) 19.98,21.2 21.855,23.074 22.54,23.074 22.976,23.51 22.976,24.776 21.7,26.051 21.7,32.903 24.6,35.803 24.6,39 30.2,44.6 37.762,44.6 38.662,45.5 41.5,45.5 42.4,46.4 v1(50.6,46.4)
GPIO3_21: P2.25 SOM1.A26 | length 52.7
  Top Layer w0.2: v1(18.6,25) 19.618,23.982 SOM1.A26@21.039,23.982
  Bottom Layer w0.2: v1(18.6,25) 19.7,26.1 19.7,33.992 21.026,35.319 21.026,38.255 29.372,46.6 36.933,46.6 37.833,47.5 40.456,47.5 41.556,48.6 45.2,48.6 46.4,49.8 46.4,50.6 47.2,51.4 48.86,51.4 P2.25@50.165,52.705
I2C1_SCL: P2.17 SOM1.A51 | length 34.1
  Top Layer w0.2: SOM1.A51@26.039,30.482 31.082,30.482 42.4,41.8 42.4,44.6 38.595,48.405 38.595,51.295 P2.17@40.005,52.705
I2C1_SDA: P2.18 SOM1.A45 | length 33.2
  Top Layer w0.2: SOM1.A45@26.039,28.982 31.582,28.982 43.6,41 43.6,46.565 40.002,50.163 P2.18@40,50.165
I2C2_SCL: P2.19 SOM1.A33 | length 48.3
  Top Layer w0.2: SOM1.A33@26.039,25.982 27.192,25.982 27.71,26.5 28.29,26.5 28.49,26.3 31.163,26.3 48.825,43.962 48.825,46.625 51.6,49.4 51.6,51 51,51.6 44.4,51.6 43.295,52.705 P2.19@42.545,52.705
I2C2_SDA: P2.20 SOM1.A35 | length 48.4
  Top Layer w0.2: SOM1.A35@26.039,26.482 27.126,26.482 27.544,26.9 28.456,26.9 28.656,26.7 30.997,26.7 48.425,44.128 48.425,46.997 51.175,49.747 51.175,50.775 51.2,50.8 50.8,51.2 47,51.2 46.4,50.6 46.4,49.8 45.6,49 43.71,49 P2.20@42.545,50.165
LCD_DATA0: P1.45 SOM1.B12 | length 20.2
  Top Layer w0.2: SOM1.B12@67.039,20.482 68.07,20.482 72.1,16.452 72.1,7.91 P1.45@75.565,4.445
LCD_DATA1: P1.46 SOM1.B10 | length 22.2
  Top Layer w0.2: SOM1.B10@67.039,19.982 68.004,19.982 71.7,16.286 71.7,7.5 74.4,4.8 74.4,3.07 P1.46@75.565,1.905
LCD_DATA2: P1.43 S1.4 SOM1.B8 | length 32.5
  Top Layer w0.2: SOM1.B8@67.039,19.482 67.938,19.482 71.3,16.12 71.3,12.7 ; v1(70.688,12.7) 71.3,12.7 ; P1.43@73.025,4.445 72.555,4.445 71.3,5.7 71.3,12.7 ; v1(74.955,15.291) 75.987,14.26 78.707,14.26 80.645,16.197 S1.4@80.645,17.51
  Bottom Layer w0.2: v1(70.688,12.7) 73.279,15.291 v1(74.955,15.291)
LCD_DATA3: P1.44 SOM1.B6 | length 24.7
  Top Layer w0.2: SOM1.B6@67.039,18.982 65.982,18.982 65.6,18.6 65.6,14.769 68.7,11.669 68.7,5.118 69,4.818 69,1.6 69.705,0.895 72.015,0.895 P1.44@73.025,1.905
LCD_DATA4: P1.41 SOM1.B2 | length 15.8
  Top Layer w0.2: SOM1.B2@67.039,17.982 66.582,17.982 66.4,17.8 66.4,15.1 69.5,12 69.5,5.45 70.485,4.465 P1.41@70.485,4.445
LCD_DATA5: P1.42 SOM1.B4 | length 19.3
  Top Layer w0.2: SOM1.B4@67.039,18.482 66.282,18.482 66,18.2 66,14.934 69.1,11.834 69.1,5.284 69.4,4.984 69.4,2.99 P1.42@70.485,1.905
LCD_DATA6: P1.39 SOM1.B1 | length 19.8
  Top Layer w0.2: SOM1.B1@72.039,17.982 72.039,17.078 72.5,16.617 72.5,8.5 v1@74.4,6.6
  Bottom Layer w0.2: P1.39@67.945,4.445 69.1,5.6 73.8,5.6 v1(74.6,6.4)
LCD_DATA7: P1.40 SOM1.B3 | length 27.3
  Top Layer w0.2: SOM1.B3@72.039,18.482 72.688,18.482 72.958,18.212 72.958,12.189 72.922,12.153 72.922,9.078 75.8,6.2 v1@76.8,6.2
  Bottom Layer w0.2: P1.40@67.945,1.905 69.04,3 76.2,3 77,3.8 v1(77,6)
LCD_DATA8: P1.37 SOM1.B5 | length 24.1
  Top Layer w0.2: SOM1.B5@72.039,18.982 72.754,18.982 73.358,18.378 73.358,12.023 73.322,11.987 73.322,10.078 v1@75.4,8
  Bottom Layer w0.2: P1.37@65.405,4.445 67.16,6.2 73.41,6.2 74.41,7.2 75,7.2 v1(75.4,7.6)
LCD_DATA9: P1.38 SOM1.B7 | length 28.4
  Top Layer w0.2: SOM1.B7@72.039,19.482 72.82,19.482 73.758,18.544 73.758,11.858 73.722,11.822 73.722,10.512 76.4,7.834 v1(76.4,7.2)
  Bottom Layer w0.2: P1.38@65.405,1.905 66.5,3 68.4,3 68.8,3.4 73.85,3.4 74.555,4.105 74.555,5.18 76.2,6.825 v1@76.2,7.2
LCD_DATA10: P1.36 SOM1.B9 | length 32.1
  Top Layer w0.2: SOM1.B9@72.039,19.982 72.913,19.982 74.2,18.695 74.2,13.91 77.391,10.719 v1(77.902,10.719)
  Bottom Layer w0.2: P1.36@62.865,1.905 62.865,2.865 64.2,4.2 64.2,4.668 66.132,6.6 73.244,6.6 75.476,8.832 75.54,8.832 77.122,10.413 77.122,10.478 77.363,10.719 v1(77.902,10.719)
LCD_DATA11: P1.34 SOM1.B11 | length 35
  Top Layer w0.2: SOM1.B11@72.039,20.482 75.162,20.482 75.644,20 76.2,20 v1(76.6,19.6)
  Bottom Layer w0.2: P1.34@60.325,1.905 61.8,3.38 61.8,5.2 64,7.4 72.913,7.4 75.145,9.632 75.209,9.632 76.322,10.745 76.322,10.809 77.1,11.587 77.1,19.1 v1(76.6,19.6)
LCD_DATA12: P1.35 SOM1.B13 | length 32.8
  Top Layer w0.2: SOM1.B13@72.039,20.982 75.228,20.982 75.81,20.4 76.7,20.4 v1(77.2,20.9)
  Bottom Layer w0.2: P1.35@62.865,4.445 65.42,7 73.079,7 75.31,9.232 75.375,9.232 76.722,10.579 76.722,10.643 77.5,11.421 77.5,20.6 v1(77.2,20.9)
LCD_DATA13: P1.33 SOM1.B15 | length 33.9
  Top Layer w0.2: SOM1.B15@72.039,21.482 75.718,21.482 v1(76.1,21.1)
  Bottom Layer w0.2: P1.33@60.325,4.445 63.68,7.8 72.747,7.8 74.979,10.032 75.043,10.032 75.922,10.91 75.922,10.975 76.7,11.753 76.7,18.566 76.366,18.9 76.31,18.9 75.333,19.877 75.333,20.333 v1(76.1,21.1)
LCD_DATA14: P1.31 SOM1.B17 | length 36.6
  Top Layer w0.2: SOM1.B17@72.039,21.982 74.7,21.982 75.218,22.5 v1(75.4,22.5)
  Bottom Layer w0.2: P1.31@57.785,4.445 58.045,4.445 62.2,8.6 72.4,8.6 74.632,10.832 74.712,10.832 75.122,11.242 75.122,11.322 75.75,11.95 75.75,18.2 74,19.95 74,20.9 75.4,22.3 v1(75.4,22.5)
